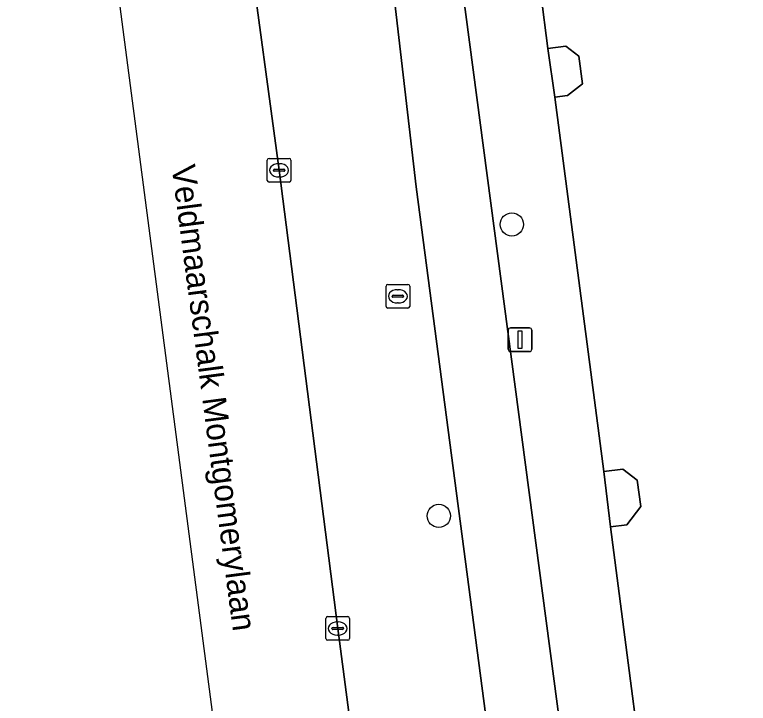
# Model space of a CAD drawing. Extents: x 161084 to 161928, y 385354 to 386522.
# Drawn here: x 161140.77 to 161171.75, y 386097.32 to 386126.41 of the extents above; entities that cross this region are included whole.
import ezdxf

# ---------------------------------------------------------------- set-up
doc = ezdxf.new("R2010")
doc.units = 0
for name, color, linetype in [('IMGEO_Berm_groen', 7, 'Continuous'), ('IMGEO_Boom', 7, 'Continuous'), ('IMGEO_Erf', 7, 'Continuous'), ('IMGEO_Fietspad_gesloten', 7, 'Continuous'), ('IMGEO_Kolk', 7, 'Continuous'), ('IMGEO_Lichtmast', 7, 'Continuous'), ('IMGEO_Openbare_ruimte_label', 7, 'Continuous'), ('IMGEO_OVBaan_gesloten', 7, 'Continuous'), ('IMGEO_Rioolput', 7, 'Continuous'), ('IMGEO_Voetpad_open', 7, 'Continuous')]:
    doc.layers.add(name, color=color, linetype=linetype)

msp = doc.modelspace()

# ---------------------------------------------------------------- linework, layer by layer
at = {"layer": 'IMGEO_Berm_groen'}
for points in [[(161163.009, 386078.911), (161157.717, 386119.144), (161156.332, 386131.161), (161154.639, 386141.624)], [(161149.083, 386140.767), (161149.318, 386139.173), (161151.938, 386119.836), (161154.412, 386100.485), (161157.079, 386080.17), (161159.857, 386058.81), (161162.806, 386036.478), (161163.181, 386034.035), (161173.593, 385955.119), (161176.3, 385935.247), (161177.056, 385929.432), (161181.599, 385894.516), (161192.506, 385812.149), (161194.437, 385797.117), (161194.675, 385795.33), (161194.813, 385794.299), (161198.275, 385794.739), (161199.988, 385781.774), (161203.044, 385758.47), (161205.621, 385758.801), (161204.389, 385768.102), (161200.818, 385794.469)]]:
    msp.add_lwpolyline(points, dxfattribs=at)
at = {"layer": 'IMGEO_Boom'}
for centre in [(161161.763, 386117.548), (161158.68, 386105.239)]:
    msp.add_circle(centre, 0.489, dxfattribs=at)
at = {"layer": 'IMGEO_Erf'}
msp.add_lwpolyline([(161162.098, 386134.231), (161163.285, 386124.974), (161164.049, 386125.075), (161164.595, 386124.655), (161164.749, 386123.483), (161164.119, 386123.001), (161163.578, 386122.93), (161165.653, 386107.11), (161166.451, 386107.214), (161167.058, 386106.748), (161167.205, 386105.633), (161166.617, 386104.868), (161165.923, 386104.777), (161167.88, 386089.711)], dxfattribs=at)
at = {"layer": 'IMGEO_Fietspad_gesloten'}
for points in [[(161148.322, 386146.572), (161148.748, 386143.581), (161154.208, 386144.369), (161154.639, 386141.624), (161156.332, 386131.161), (161157.717, 386119.144), (161163.009, 386078.911)], [(161166.599, 386075.195), (161159.109, 386131.85), (161158.613, 386135.495), (161158.527, 386136.476), (161158.508, 386136.957), (161158.694, 386138.756), (161158.914, 386139.531)]]:
    msp.add_lwpolyline(points, dxfattribs=at)
at = {"layer": 'IMGEO_Kolk'}
for p, q in [((161151.437, 386119.41), (161151.437, 386120.262)), ((161151.512, 386120.336), (161152.364, 386120.336)), ((161152.438, 386120.262), (161152.438, 386119.41)), ((161151.696, 386119.83), (161151.696, 386119.842)), ((161151.739, 386119.879), (161152.137, 386119.879)), ((161151.925, 386120.116), (161151.95, 386120.116)), ((161152.18, 386119.842), (161152.18, 386119.83)), ((161152.134, 386119.793), (161151.736, 386119.793)), ((161151.948, 386119.556), (161151.923, 386119.556)), ((161152.364, 386119.336), (161151.512, 386119.336)), ((161153.986, 386100.985), (161154.838, 386100.985)), ((161153.911, 386100.059), (161153.911, 386100.911)), ((161154.399, 386100.765), (161154.424, 386100.765)), ((161154.912, 386100.911), (161154.912, 386100.059)), ((161154.17, 386100.479), (161154.17, 386100.491)), ((161154.608, 386100.442), (161154.21, 386100.442)), ((161154.213, 386100.528), (161154.611, 386100.528)), ((161154.654, 386100.491), (161154.654, 386100.479)), ((161154.422, 386100.205), (161154.397, 386100.205)), ((161154.838, 386099.985), (161153.986, 386099.985))]:
    msp.add_line(p, q, dxfattribs=at)
for points in [[(161151.437, 386119.41), (161151.437, 386120.262)], [(161151.512, 386120.336), (161152.364, 386120.336)], [(161152.438, 386120.262), (161152.438, 386119.41)], [(161152.364, 386119.336), (161151.512, 386119.336)], [(161153.986, 386100.985), (161154.838, 386100.985)], [(161153.911, 386100.059), (161153.911, 386100.911)], [(161154.912, 386100.911), (161154.912, 386100.059)], [(161154.838, 386099.985), (161153.986, 386099.985)]]:
    msp.add_lwpolyline(points, dxfattribs=at)
for centre, radius, start, end in [((161151.514, 386120.26), 0.0765, 91.552, 178.448), ((161151.514, 386120.26), 0.0765, 91.552, 178.448), ((161152.362, 386120.26), 0.0765, 1.552, 88.448), ((161152.362, 386120.26), 0.0765, 1.552, 88.448), ((161151.736, 386119.839), 0.0403, 85.8775, 175.7526), ((161152.141, 386119.841), 0.0386, 1.7309, 96.639), ((161151.733, 386119.829), 0.0366, 178.938, 274.7102), ((161152.137, 386119.836), 0.043, 264.8664, 352.4533), ((161151.514, 386119.412), 0.0765, 181.552, 268.448), ((161151.514, 386119.412), 0.0765, 181.552, 268.448), ((161152.362, 386119.412), 0.0765, 271.552, 358.448), ((161152.362, 386119.412), 0.0765, 271.552, 358.448), ((161153.988, 386100.909), 0.0765, 91.552, 178.448), ((161153.988, 386100.909), 0.0765, 91.552, 178.448), ((161154.836, 386100.909), 0.0765, 1.552, 88.448), ((161154.836, 386100.909), 0.0765, 1.552, 88.448), ((161154.21, 386100.488), 0.0403, 85.8775, 175.7526), ((161154.207, 386100.478), 0.0366, 178.938, 274.7102), ((161154.611, 386100.485), 0.043, 264.8664, 352.4533), ((161154.615, 386100.49), 0.0386, 1.7309, 96.639), ((161153.988, 386100.061), 0.0765, 181.552, 268.448), ((161153.988, 386100.061), 0.0765, 181.552, 268.448), ((161154.836, 386100.061), 0.0765, 271.552, 358.448), ((161154.836, 386100.061), 0.0765, 271.552, 358.448)]:
    msp.add_arc(centre, radius, start, end, dxfattribs=at)
for centre, major_axis, ratio, start_param, end_param in [((161151.924, 386119.836), (-0.387, 0.002), 0.722429, 4.712389, 7.853982), ((161151.949, 386119.836), (-0.39, 0.002), 0.717154, 1.570796, 4.712389), ((161154.398, 386100.485), (-0.387, 0.002), 0.722429, 4.712389, 7.853982), ((161154.423, 386100.485), (-0.39, 0.002), 0.717154, 1.570796, 4.712389)]:
    msp.add_ellipse(centre, major_axis=major_axis, ratio=ratio, start_param=start_param, end_param=end_param, dxfattribs=at)
at = {"layer": 'IMGEO_Lichtmast'}
for p, q in [((161161.613, 386112.282), (161161.613, 386113.082)), ((161161.613, 386113.082), (161161.613, 386112.282)), ((161161.713, 386113.182), (161162.503, 386113.182)), ((161162.503, 386113.182), (161161.713, 386113.182)), ((161162.603, 386113.082), (161162.603, 386112.282)), ((161162.603, 386112.282), (161162.603, 386113.082)), ((161162.503, 386112.182), (161161.713, 386112.182)), ((161161.713, 386112.182), (161162.503, 386112.182))]:
    msp.add_line(p, q, dxfattribs=at)
msp.add_lwpolyline([(161162.033, 386113.057), (161162.183, 386113.057), (161162.183, 386112.307), (161162.033, 386112.307), (161162.033, 386113.057)], dxfattribs=at)
for centre, start, end in [((161161.713, 386113.082), 90, 180), ((161161.713, 386113.082), 90, 180), ((161162.503, 386113.082), 0, 90), ((161162.503, 386113.082), 360, 90), ((161161.713, 386112.282), 180, 270), ((161161.713, 386112.282), 180, 270), ((161162.503, 386112.282), 270, 0), ((161162.503, 386112.282), 270, 0)]:
    msp.add_arc(centre, 0.1, start, end, dxfattribs=at)
at = {"layer": 'IMGEO_OVBaan_gesloten'}
for points in [[(161140.774, 386160.649), (161167.141, 385959.129), (161182.706, 385840.813), (161196.575, 385735.387)], [(161181.599, 385894.516), (161177.056, 385929.432), (161176.3, 385935.247), (161173.593, 385955.119), (161163.181, 386034.035), (161162.806, 386036.478), (161159.857, 386058.81), (161157.079, 386080.17), (161154.412, 386100.485), (161151.938, 386119.836), (161149.318, 386139.173), (161149.083, 386140.767), (161148.748, 386143.581), (161148.322, 386146.572), (161148.295, 386146.826), (161147.793, 386150.726), (161146.819, 386158.091)]]:
    msp.add_lwpolyline(points, dxfattribs=at)
at = {"layer": 'IMGEO_Rioolput'}
for p, q in [((161156.451, 386114.088), (161156.451, 386114.94)), ((161156.526, 386115.014), (161157.378, 386115.014)), ((161157.452, 386114.94), (161157.452, 386114.088)), ((161156.939, 386114.794), (161156.964, 386114.794)), ((161156.71, 386114.508), (161156.71, 386114.52)), ((161157.148, 386114.471), (161156.75, 386114.471)), ((161156.753, 386114.557), (161157.151, 386114.557)), ((161157.194, 386114.52), (161157.194, 386114.508)), ((161157.378, 386114.014), (161156.526, 386114.014)), ((161156.962, 386114.234), (161156.937, 386114.234))]:
    msp.add_line(p, q, dxfattribs=at)
for points in [[(161156.451, 386114.088), (161156.451, 386114.94)], [(161156.526, 386115.014), (161157.378, 386115.014)], [(161157.452, 386114.94), (161157.452, 386114.088)], [(161157.378, 386114.014), (161156.526, 386114.014)]]:
    msp.add_lwpolyline(points, dxfattribs=at)
for centre, radius, start, end in [((161156.528, 386114.938), 0.0765, 91.552, 178.448), ((161156.528, 386114.938), 0.0765, 91.552, 178.448), ((161157.376, 386114.938), 0.0765, 1.552, 88.448), ((161157.376, 386114.938), 0.0765, 1.552, 88.448), ((161156.75, 386114.517), 0.0403, 85.8775, 175.7526), ((161156.747, 386114.507), 0.0366, 178.938, 274.7102), ((161157.151, 386114.514), 0.043, 264.8664, 352.4533), ((161157.155, 386114.519), 0.0386, 1.7309, 96.639), ((161156.528, 386114.09), 0.0765, 181.552, 268.448), ((161156.528, 386114.09), 0.0765, 181.552, 268.448), ((161157.376, 386114.09), 0.0765, 271.552, 358.448), ((161157.376, 386114.09), 0.0765, 271.552, 358.448)]:
    msp.add_arc(centre, radius, start, end, dxfattribs=at)
for centre, major_axis, ratio, start_param, end_param in [((161156.938, 386114.514), (-0.387, 0.002), 0.722429, 4.712389, 7.853982), ((161156.963, 386114.514), (-0.39, 0.002), 0.717154, 1.570796, 4.712389)]:
    msp.add_ellipse(centre, major_axis=major_axis, ratio=ratio, start_param=start_param, end_param=end_param, dxfattribs=at)
at = {"layer": 'IMGEO_Voetpad_open'}
msp.add_lwpolyline([(161167.88, 386089.711), (161165.923, 386104.777), (161165.653, 386107.11), (161163.578, 386122.93), (161163.285, 386124.974), (161162.098, 386134.231), (161162.09, 386134.335), (161162.064, 386135.164), (161162.112, 386135.991), (161162.234, 386136.811), (161162.429, 386137.617), (161162.695, 386138.402), (161163.031, 386139.16), (161163.432, 386139.886), (161163.897, 386140.572), (161164.421, 386141.214), (161158.914, 386139.531), (161158.694, 386138.756), (161158.508, 386136.957), (161158.527, 386136.476), (161158.613, 386135.495), (161159.109, 386131.85), (161166.599, 386075.195)], dxfattribs=at)
for points in [[(161163.578, 386122.93), (161164.119, 386123.001), (161164.749, 386123.483), (161164.595, 386124.655), (161164.049, 386125.075), (161163.285, 386124.974)], [(161165.923, 386104.777), (161166.617, 386104.868), (161167.205, 386105.633), (161167.058, 386106.748), (161166.451, 386107.214), (161165.653, 386107.11)]]:
    msp.add_lwpolyline(points, close=True, dxfattribs=at)

# ---------------------------------------------------------------- texts
at = {"layer": 'IMGEO_Openbare_ruimte_label'}
msp.add_text('Veldmaarschalk Montgomerylaan', height=1, rotation=277.5303, dxfattribs=at).set_placement((161147.394, 386120.004))

doc.saveas('drawing.dxf')
